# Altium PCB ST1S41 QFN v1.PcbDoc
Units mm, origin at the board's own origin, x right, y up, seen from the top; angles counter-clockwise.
Board outline 152.4 x 101.6 mm, 2 copper layers (Top Layer, Bottom Layer); 13 components, 1 nets, 36 pads, 21 vias.
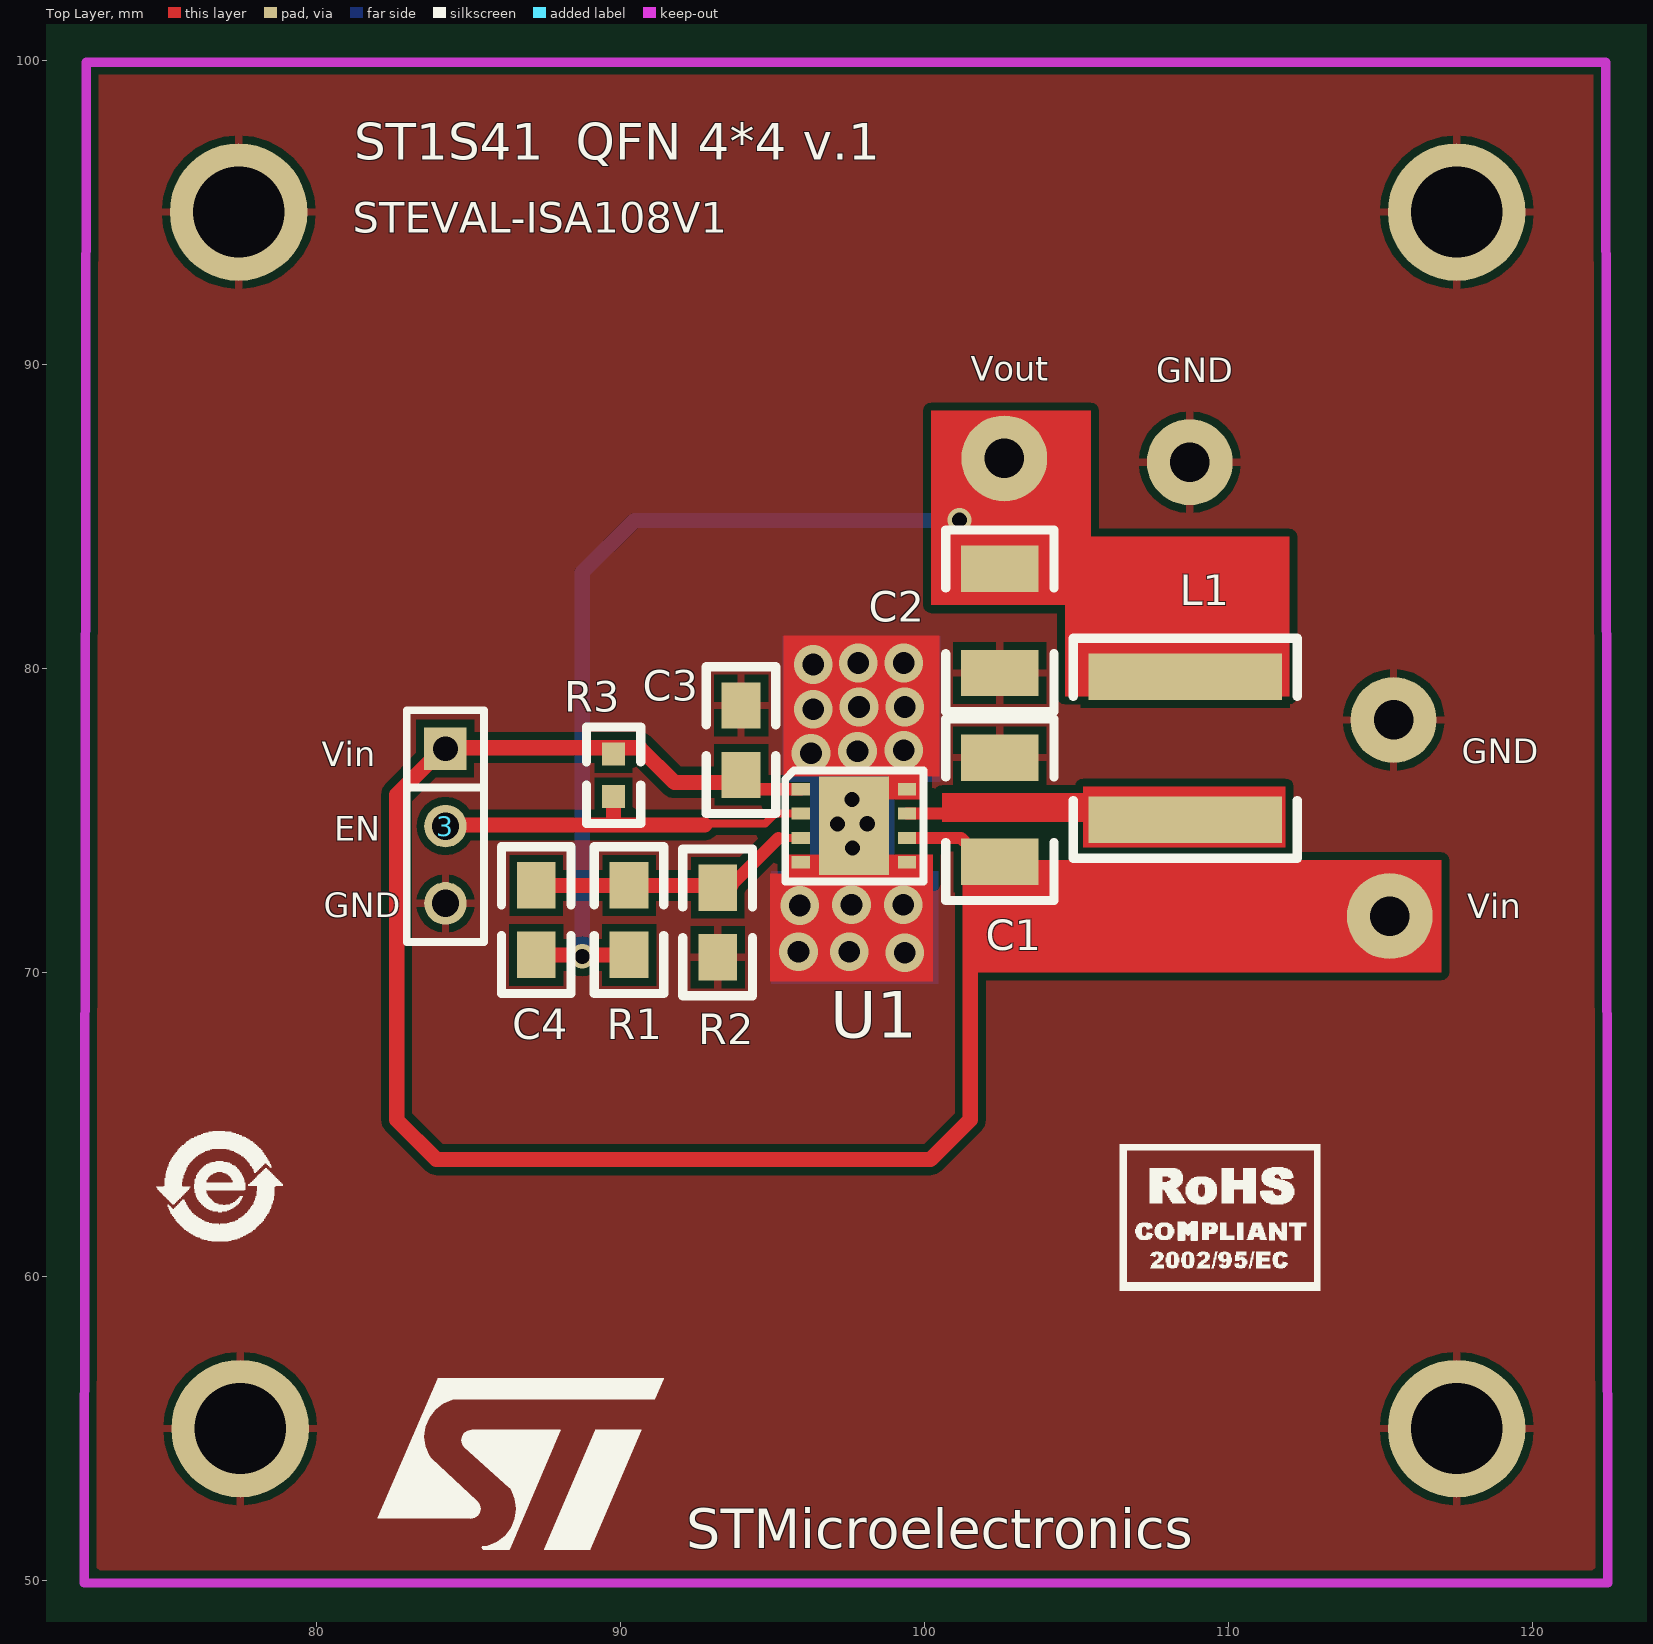
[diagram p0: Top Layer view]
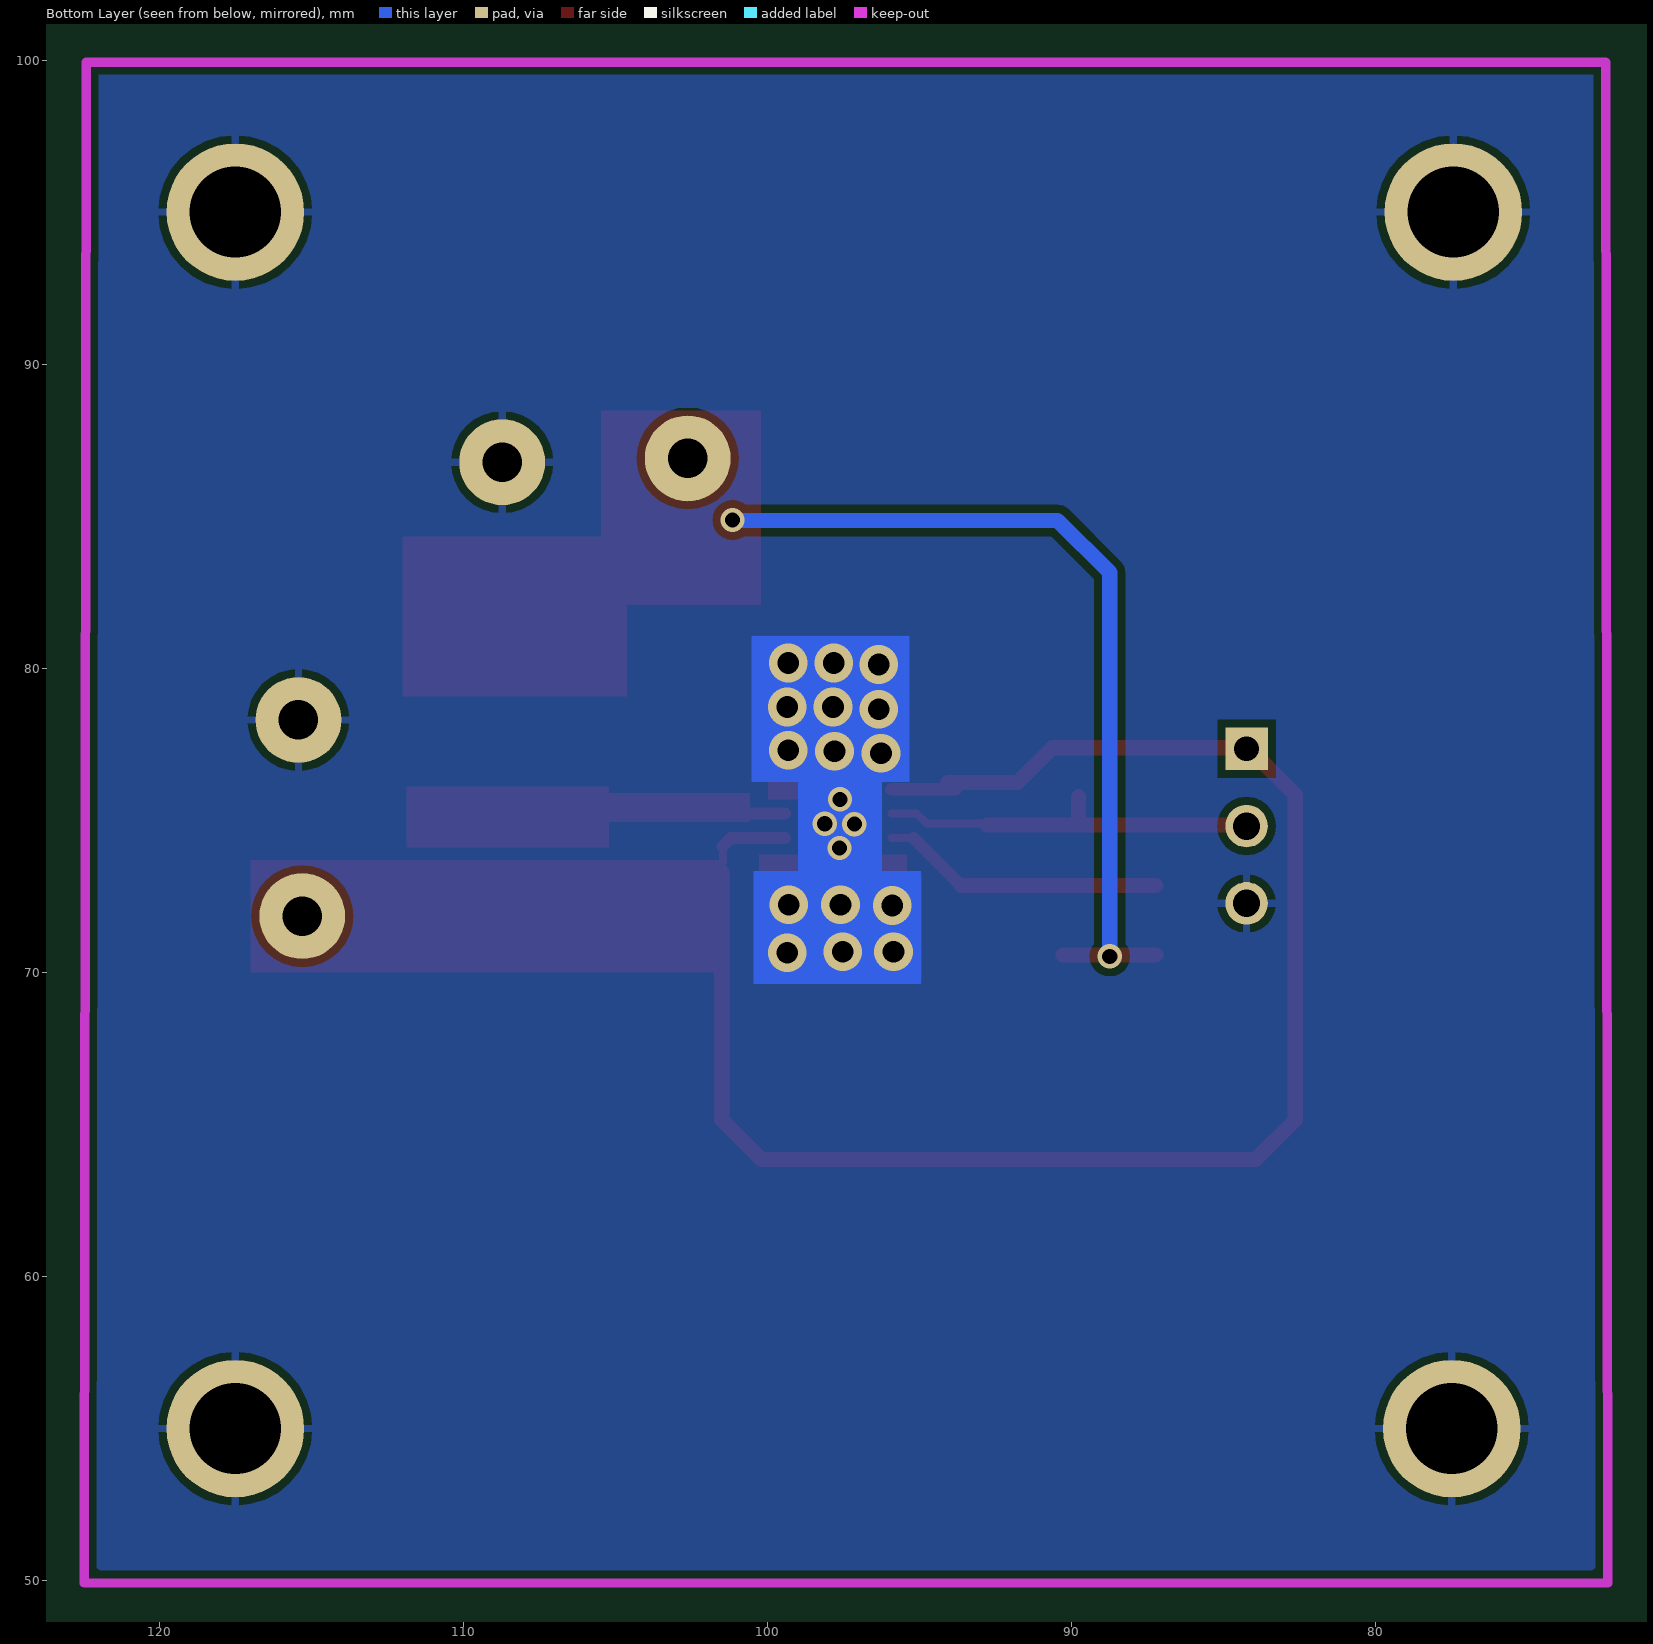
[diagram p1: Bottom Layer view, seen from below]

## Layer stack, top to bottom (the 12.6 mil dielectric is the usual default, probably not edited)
Top Layer: signal copper 0.0356
Dielectric: dielectric 0.32, FR-4, Dk 4.8
Bottom Layer: signal copper 0.0356

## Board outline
25.4,25.4 177.8,25.4 177.8,127 25.4,127

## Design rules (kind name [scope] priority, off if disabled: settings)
Clearance [All] p1: gap=0.254
ComponentClearance [All] p1: gap=0.254 collisioncheckmode=3 verticalgap=0.254
PolygonConnect [All] p1: connectstyle=Relief reliefconductorwidth=0.254 reliefentries=4 polygonreliefangle="90 Angle"
RoutingVias [All] p1: holewidth=0.711 width=1.27 viastyle="Through Hole" minholewidth=0.711 minwidth=1.27 maxholewidth=0.711 maxwidth=1.27
SolderMaskExpansion [All] p1: expansion=0.102
TestPointUsage [All] p1: valid=0 allowmultiple=FALSE
Testpoint [All] p1: side=15 testpointundercomponent=TRUE minsize=1.016 maxsize=2.54 preferedsize=1.524 minholesize=0 maxholesize=1.016 preferedholesize=0.813 testpointgrid=0.025 style=1023 order=0123456789
Width [All] p1: maxlimit=0.254 minlimit=0.254 preferedwidth=0.254
18 further rules are at their usual default settings.

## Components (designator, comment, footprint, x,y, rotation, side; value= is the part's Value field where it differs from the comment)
3 "3pin Male" SIP3 84.25,77.35 r270 top
C1 "10µF" 1210 102.479,77.062 r270 top
C2 "22µF" 1210 102.479,83.274 r270 top
C3 "1µF" 0805 93.97,76.492 r90 top
C4 "NC" 0805 87.239,70.574 r90 top
L1 "3.3µH" 1825 108.575,79.718 r270 top
R1 "62K5" 0805 90.287,70.574 r90 top
R2 "20K" 0805 93.2,70.5 r90 top
R3 "NC" 0603 89.779,77.178 r270 top
STMicroelectronics "" LOGOUFFICIALE_MEDIUM 82.25,51.275 r0 top
U1 "ST1S40" "VFDFPN 8L 4X4 0,8 ST1S10" 99.431,73.622 r90 top
? "" CH_ROHS 76.95,62.925 r0 top
? "Comment" EU_ROHS_1 109.591,61.43 r0 top

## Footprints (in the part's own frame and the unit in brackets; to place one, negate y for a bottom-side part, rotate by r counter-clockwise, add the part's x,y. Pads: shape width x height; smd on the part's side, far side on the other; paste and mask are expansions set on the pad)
0603 [mil]
  rect 30x30 smd: 1(0,0) 2(55,0)
  silkscreen extent -35,-35 90,35
0805 [mil]
  rect 60x50 smd: 1(0,0) 2(90,0)
  silkscreen extent -50,-45 140,45
1210 [mil]
  rect 60x100 smd: 1(0,0) 2(135,0)
  silkscreen extent -50,-70 185,70
1825 [mil]
  rect 60x250 smd: 1(0,0) 2(185,0)
  silkscreen extent -50,-145 235,145
CH_ROHS [mm]
  silkscreen extent -2.21,-1.75 1.96,1.85
EU_ROHS_1 [mm]
  silkscreen extent -3.17,-1.88 3.43,2.92
LOGOUFFICIALE_MEDIUM [mm]
  silkscreen extent -0.23,-0.26 9.17,5.38
SIP3 [mm]
  rect 1.4x1.4 hole 0.813: 1(0,0)
  round 1.4 hole 0.9: 2(2.54,0) 3(5.08,0)
  silkscreen extent -1.27,-1.27 6.35,1.27
"VFDFPN 8L 4X4 0,8 ST1S10" [mil]
  rect 15.73x23.6 smd: 1(0,0) 2(31.5,0) 3(63,0) 4(94.5,0) 5(94.5,137.8) 6(63,137.8) 7(31.5,137.8) 8(0,137.8)
  rect 127.57x90.53 smd: 9(47.25,68.9)

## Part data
C1: "X7R C3225X7R1E106K TDK"
C2: "X7R C3225X7R1C226M TDK"
C3: "X7R"
L1: "Coilcraft   XAL5030-332ME"

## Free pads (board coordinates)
  round 4.524 hole 3: 0(77.45,95) 1(117.5,95) 2(117.5,55) 3(77.5,55)
  round 2.824 hole 1.3: 0(102.625,86.9) 1(108.725,86.775) 2(115.425,78.3) 3(115.3,71.85)

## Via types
v1: diameter 1.27, hole 0.711, Top Layer to Bottom Layer, 15 vias
v2: diameter 0.8, hole 0.5, Top Layer to Bottom Layer, 6 vias

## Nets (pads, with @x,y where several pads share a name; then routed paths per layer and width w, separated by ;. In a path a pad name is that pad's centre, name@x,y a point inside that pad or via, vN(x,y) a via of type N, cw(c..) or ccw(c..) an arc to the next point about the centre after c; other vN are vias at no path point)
GND: 3.3 C1.1 C2.2 C3.2 pad.0@77.45,95 pad.1 pad.2 pad.3@77.5,55 R2.1 U1.9
  other v1: 99.35,70.65 95.858,70.675 97.533,70.675 95.9,72.2 97.6,72.225 99.3,72.225 96.271,77.2 97.8,77.275 99.325,77.3 96.346,78.65 97.85,78.725 99.35,78.725 96.346,80.125 97.825,80.175 99.325,80.175
  other v2: 97.633,74.088 97.146,74.875 98.121,74.888 97.621,75.688
pads on no net: 3.1 3.2 C1.2 C2.1 C3.1 C4.1 C4.2 L1.1 L1.2 R1.1 R1.2 R2.2 R3.1 R3.2 U1.1 U1.2 U1.3 U1.4 U1.5 U1.6 U1.7 U1.8
copper on no net: | length 108.6
  Top Layer w0.25: 92.5,74.895 94.766,74.895
  Top Layer w0.254: 94.766,74.895 95.093,75.223 95.93,75.223 ; 95.205,74.423 95.93,74.423 ; 101.463,73.622 101.463,74.13
  Top Layer w0.4: 93.643,72.86 95.205,74.423 ; 93.808,76.023 95.93,76.023 ; 99.431,74.423 101.198,74.423 101.477,74.144 ; 99.431,75.223 100.793,75.223
  Top Layer w0.5: 84.25,74.847 92.775,74.85 ; 87.239,70.574 90.287,70.574 ; 87.239,72.86 90.287,72.86 93.643,72.86 ; 89.779,74.852 89.779,75.781 ; 94.072,76.236 94.068,76.24 91.781,76.24 90.638,77.383 84.191,77.383 82.646,75.838 82.646,65.154 83.95,63.85 100.2,63.85 101.508,65.158 101.508,73.3
  Bottom Layer w0.5: v2(88.746,70.525) 88.746,83.146 90.463,84.863 v2@101.15,84.863
  other v2: 101.15,84.875

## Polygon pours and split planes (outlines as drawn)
GND on Top Layer "GND" (solid, pour order 1000): 72.436,99.925 122.405,99.925 122.405,49.986 122.466,49.925 72.375,49.925
GND on Bottom Layer "GND" (solid, pour order 1001): 72.436,99.925 122.405,99.925 122.466,99.864 122.466,49.925 72.375,49.925

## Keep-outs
Keep-Out Layer:
  lines w0.305: 72.375,49.925 122.466,49.925 122.405,99.925 72.436,99.925 72.375,49.925

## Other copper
Top Layer:
  rectangle net GND: 94.921,69.7 100.283,73.25
  rectangle net GND: 95.371,76.438 100.496,81.075
  rectangle: 98.871,72.925 99.084,73.169
  rectangle: 95.421,72.925 100.283,73.875
  rectangle: 98.796,75.686 99.984,76.55
  rectangle: 96.277,76.438 99.084,76.697
  rectangle: 100.221,82.075 105.471,88.475
  rectangle: 104.621,79.075 111.996,84.325
  rectangle: 105.221,74.113 111.871,76.113
  rectangle: 101.508,70 116.996,73.688
  rectangle: 100.583,74.938 111.571,75.9
Bottom Layer:
  rectangle net GND: 96.244,73.15 96.503,76.35
  rectangle net GND: 98.763,73.181 99.022,76.35
  rectangle net GND: 94.958,69.625 100.458,73.338
  rectangle net GND: 95.333,76.263 100.533,81.063
  rectangle: 96.503,73.15 98.763,76.35

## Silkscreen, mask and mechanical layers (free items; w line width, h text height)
Top Overlay:
  lines w0.254: 95.421,72.988 99.971,72.988 99.971,76.638 95.708,76.638 95.421,76.35 95.421,72.988
  text "ST1S41  QFN 4*4 v.1" at 81.256,96.715 h1.2
  text "STEVAL-ISA108V1" at 81.207,94.315 h1
  text "Vout" at 101.525,89.45 h0.8
  text "GND" at 107.625,89.4 h0.8
  text "GND" at 117.671,76.875 h0.8
  text "Vin" at 80.175,76.775 h0.8
  text "EN" at 80.6,74.325 h0.8
  text "GND" at 80.246,71.813 h0.8
  text "Vin" at 117.846,71.775 h0.8
Top Solder:
  rectangle: 98.871,75.688 100.321,76.5
  rectangle: 99.771,75.813 100.246,76.213
  rectangle: 99.783,75.013 100.258,75.413
  rectangle: 99.771,74.225 100.246,74.625
  rectangle: 99.771,73.425 100.246,73.825
  rectangle: 95.221,73.475 95.696,73.875
  rectangle: 95.108,74.213 95.583,74.613
  rectangle: 95.108,75.025 95.583,75.425
  rectangle: 95.108,75.825 95.583,76.225
  text "VG" at 120.05,50.675 h1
